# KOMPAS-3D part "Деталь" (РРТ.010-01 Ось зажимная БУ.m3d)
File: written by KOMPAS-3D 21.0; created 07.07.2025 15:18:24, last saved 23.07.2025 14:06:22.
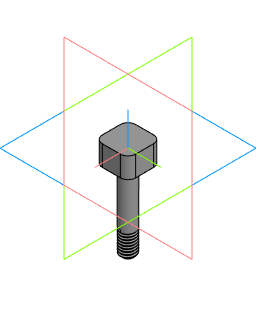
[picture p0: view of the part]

Document properties: Автор: User; Полное имя файла: C:\Users\Alexey\Documents\Bitrix24\Производство\технологии\KazanTarget\эксперименты\ручной ротатор\РРТ.010-01 Ось зажимная БУ\РРТ.010 Ось зажимная БУ.m3d

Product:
- Part/product: Деталь
    Масса: 0.016583
    Форматы листов документа: A4

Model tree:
1. Эскиз:1
2. Элемент выдавливания:1
     Расстояние 1 = 3
3. Эскиз:2  (with: Элемент выдавливания:1)
4. Элемент выдавливания:2  (with: ЛСК (Внешняя цилиндрическая ступень с метрической резьбой):1, Внешняя цилиндрическая ступень с метрической резьбой:1, Плоскость XY, Плоскость ZX, Плоскость ZY, Ось X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)
     Расстояние 1 = 24; Ось X. Z = 1; Ось Y. X = 1; Ось Z. Y = 1; Точка начала. Z = -24; Угол 1 = 360; Угол 1 = 360; Угол 1 = 360
5. Эскиз выреза профиля резьбы (Внешняя цилиндрическая ступень с метрической резьбой):1  (with: Винтовая линия (Внешняя цилиндрическая ступень с метрической резьбой):1, Булева операция:2)
     Расстояние = 12; Число витков = 10; Шаг = 1; Высота = 10; Диаметр 1 = 6; Диаметр 2 = 10; Угол = 270; Число витков = 2.5; Шаг = 1; Высота = 2.5; Диаметр 1 = 6; Диаметр 2 = 8.02013; Угол наклона образующей = 22; Угол = 270
6. Внешняя цилиндрическая ступень с метрической резьбой:1
7. Скругление:2  (with: Элемент выдавливания:1)
     Радиус = 3
8. Элемент выдавливания:3  (with: Элемент выдавливания:1)
     Расстояние 1 = 5
9. Скругление:3  (with: Элемент выдавливания:3)
     Радиус = 0.4

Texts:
  [Data]  D=6  L=12  Len_Th=10  Step=1  Tip_Step=1  PoleTh=[6g]  Flag_Left_Thread=2  ExistThrough=0  TypeThrough=1  SubType=0  DiamF=0  Flag_FaskOnGOST=1  Fask=1  FAngle=45  F=3  R=1  R1=0.5  R2=0  Df=1.5  Flag_NoStandart=2  NS_Prototype=0  NTDThrough=0  MarkRing=005-007-14  MarkThread=М6-6g
  SHAFT3D
  (VCThMetrO_1_D<=0||VCThMetrO_1_D>5e+7)?25:VCThMetrO_1_D
  (VCThMetrO_1_L<=0||VCThMetrO_1_L>5e+7)?25:VCThMetrO_1_L
  Плоскость начала спирали резьбы (Внешняя цилиндрическая ступень с метрической резьбой):1
  Эскиз для винтовой линии (Внешняя цилиндрическая ступень с метрической резьбой):1
  Плоскость начала конической спирали резьбы (Внешняя цилиндрическая ступень с метрической резьбой):1
  Коническая винтовая линия (Внешняя цилиндрическая ступень с метрической резьбой):1
  Вырез профиля резьбы (Внешняя цилиндрическая ступень с метрической резьбой):1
